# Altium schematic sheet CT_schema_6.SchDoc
size 251 x 245 mm
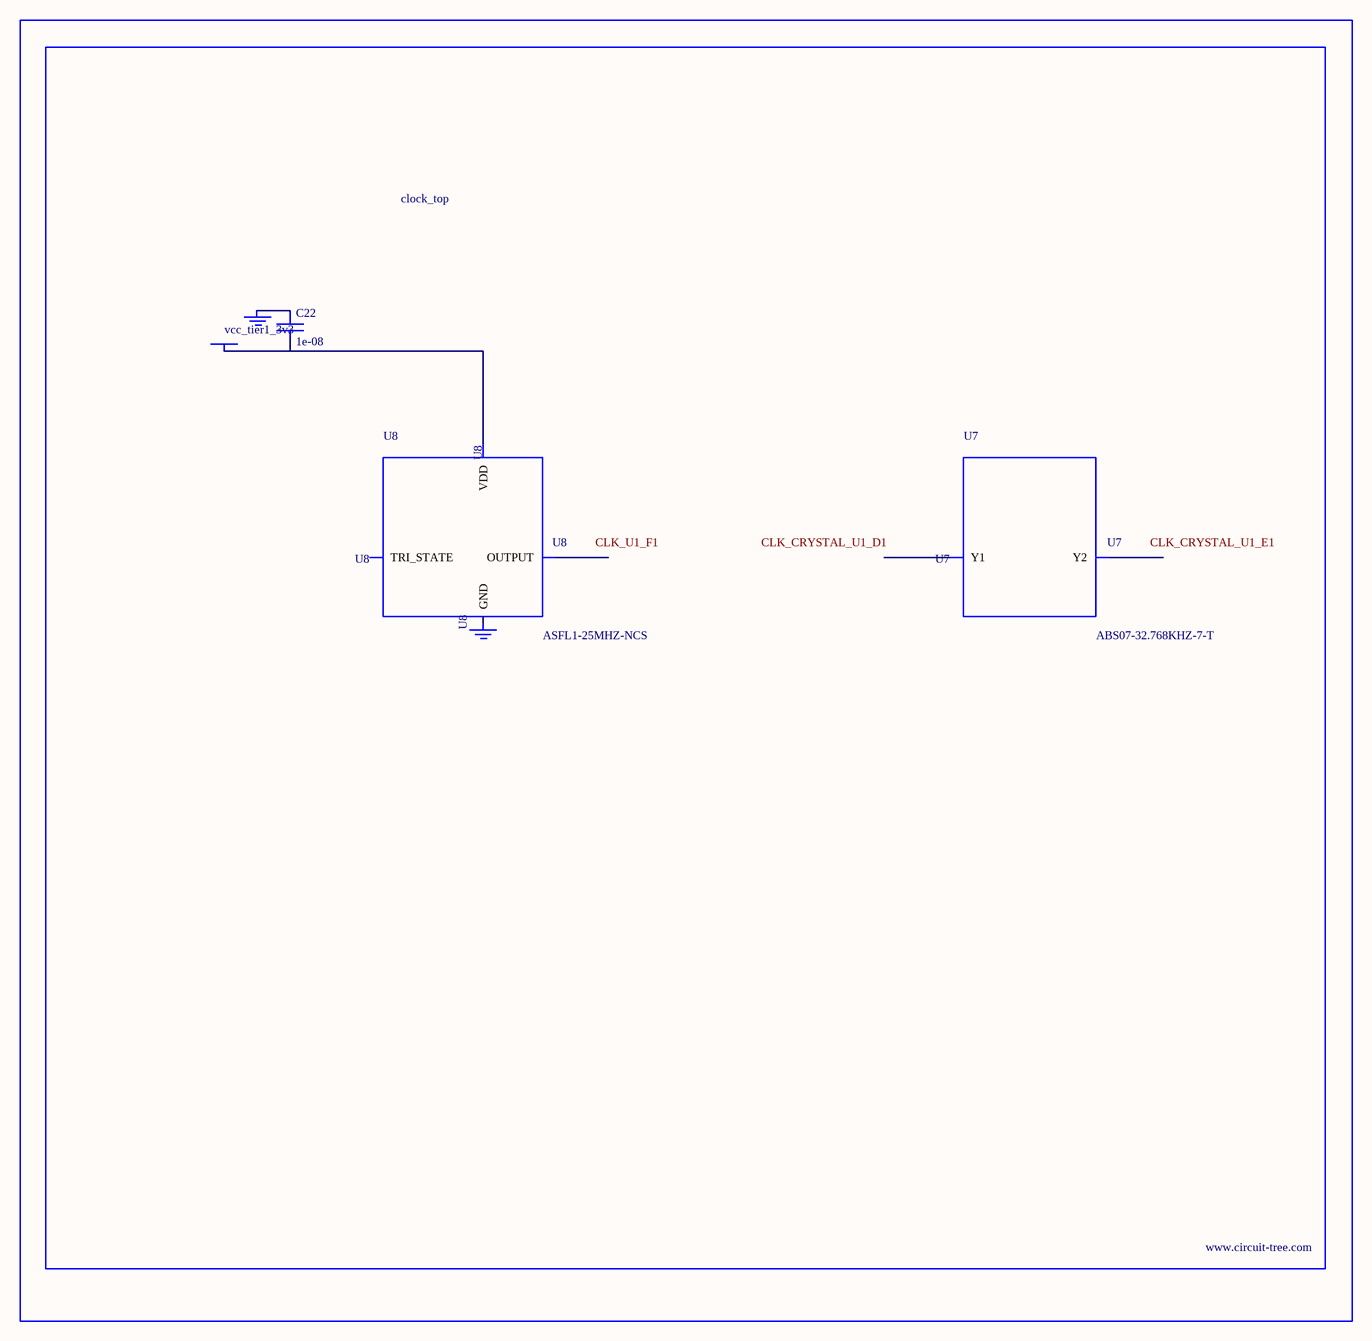
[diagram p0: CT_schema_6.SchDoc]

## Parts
BORDER5  (no value)
C22  1e-08  [C0402]
GND_INSTANCE_5_0  (no value)
GND_INSTANCE_5_1  (no value)
POWER_INSTANCE_5_0  vcc_tier1_3v3
U7  ABS07-32.768KHZ-7-T  [ABS07-32.768KHZ-7-T]
U8  ASFL1-25MHZ-NCS  [ASFL1]

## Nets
NetC22_1: C22.1 GND_INSTANCE_5_0.0(GND)
NetC22_2: C22.2 POWER_INSTANCE_5_0.0(PWR) U8.4(VDD)

Not connected (* = marked no-connect by the designer): GND_INSTANCE_5_1 0(GND); U7 1(Y1) 2(Y2); U8 1(TRI_STATE) 2(GND) 3(OUTPUT)

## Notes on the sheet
- Labels drawn without touching a wire or pin: CLK_CRYSTAL_U1_D1, CLK_CRYSTAL_U1_E1, CLK_U1_F1

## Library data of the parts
BORDER5 = BORDER_PAGE5
C22 = C0402C103K3RAC
GND_INSTANCE_5_0 GND_INSTANCE_5_1 = GND
POWER_INSTANCE_5_0 = PWR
